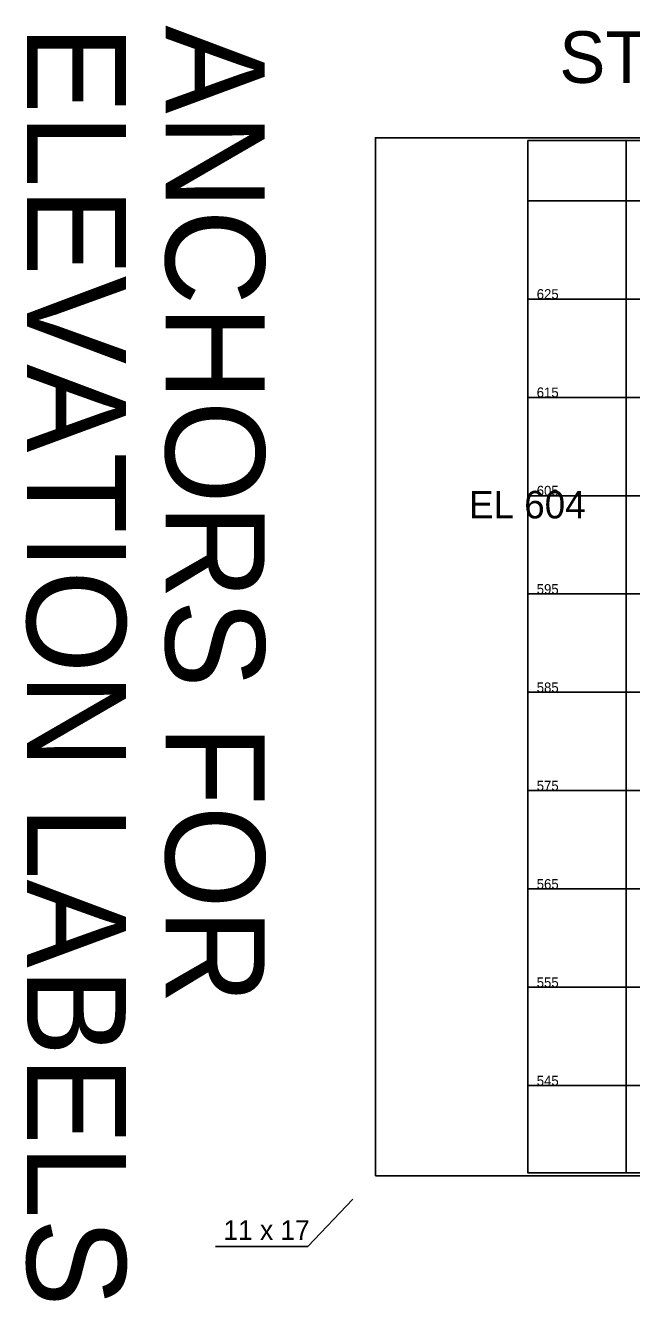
# Model space of a CAD drawing. Extents: x 278618 to 280654, y 171155 to 171855.
# Drawn here: x 280385.6 to 280447.2, y 171175.9 to 171305.6 of the extents above; entities that cross this region are included whole.
import ezdxf

# ---------------------------------------------------------------- set-up
doc = ezdxf.new("R2010")
doc.units = 0
for name, color, linetype in [('Geotech Sheets and Borders Cell', 7, 'Continuous'), ('Old_Level_39', 7, 'Continuous'), ('Prop Strc Sect_ Grid - minor', 7, 'Continuous'), ('Prop Strc Sect_ Misc - User Comment (Tx - small)', 7, 'Continuous'), ('Scratch_Level_0', 7, 'Continuous'), ('Scratch_Level_2', 7, 'Continuous'), ('Sheet Plot Border Inside CELL', 7, 'Continuous')]:
    doc.layers.add(name, color=color, linetype=linetype)

msp = doc.modelspace()

# ---------------------------------------------------------------- linework, layer by layer
at = {"layer": 'Geotech Sheets and Borders Cell'}
msp.add_lwpolyline([(280436.69, 171293.86), (280586.69, 171293.86), (280586.69, 171188.86), (280436.69, 171188.86)], close=True, dxfattribs=at)
at = {"layer": 'Prop Strc Sect_ Grid - minor'}
for p, q in [((280446.69, 171188.86), (280446.69, 171293.86)), ((280534.1, 171287.74), (280436.69, 171287.74)), ((280586.69, 171277.74), (280436.69, 171277.74)), ((280586.69, 171267.74), (280436.69, 171267.74)), ((280586.69, 171257.74), (280436.69, 171257.74)), ((280586.69, 171247.74), (280436.69, 171247.74)), ((280586.69, 171237.74), (280436.69, 171237.74)), ((280586.69, 171227.74), (280436.69, 171227.74)), ((280586.69, 171217.74), (280436.69, 171217.74)), ((280586.69, 171207.74), (280436.69, 171207.74)), ((280586.69, 171197.74), (280436.69, 171197.74))]:
    msp.add_line(p, q, dxfattribs=at)
at = {"layer": 'Scratch_Level_0'}
msp.add_line((280421.17, 171188.58), (280421.17, 171188.58), dxfattribs=at)
msp.add_lwpolyline([(280404.91, 171181.38), (280414.29, 171181.38), (280418.88, 171186.18)], dxfattribs=at)
at = {"layer": 'Sheet Plot Border Inside CELL'}
msp.add_lwpolyline([(280421.17, 171188.58), (280587.94, 171188.58), (280587.94, 171294.14), (280421.17, 171294.14)], close=True, dxfattribs=at)

# ---------------------------------------------------------------- texts
at = {"layer": 'Geotech Sheets and Borders Cell'}
for s, p in [('625', (280437.58, 171277.74)), ('615', (280437.58, 171267.74)), ('605', (280437.58, 171257.74)), ('595', (280437.58, 171247.74)), ('585', (280437.58, 171237.74)), ('575', (280437.58, 171227.74)), ('565', (280437.58, 171217.74)), ('555', (280437.58, 171207.74)), ('545', (280437.58, 171197.74))]:
    msp.add_text(s, height=1.001, dxfattribs=at).set_placement(p)
at = {"layer": 'Old_Level_39'}
msp.add_text('EL 604', height=2.8, dxfattribs=at).set_placement((280430.69, 171255.43))
at = {"layer": 'Prop Strc Sect_ Misc - User Comment (Tx - small)'}
for s, p in [('ANCHORS FOR', (280399.83, 171305.58)), ('ELEVATION LABELS', (280385.72, 171305.58))]:
    msp.add_text(s, height=10.0769, rotation=270, dxfattribs=at).set_placement(p)
at = {"layer": 'Scratch_Level_0'}
msp.add_text('11 x 17', height=2, dxfattribs=at).set_placement((280405.72, 171182.05))
at = {"layer": 'Scratch_Level_2'}
msp.add_text('STRUCTURE PROFILE SHEET, ENGLISH', height=5.25, dxfattribs=at).set_placement((280439.88, 171299.72))

doc.saveas('drawing.dxf')
